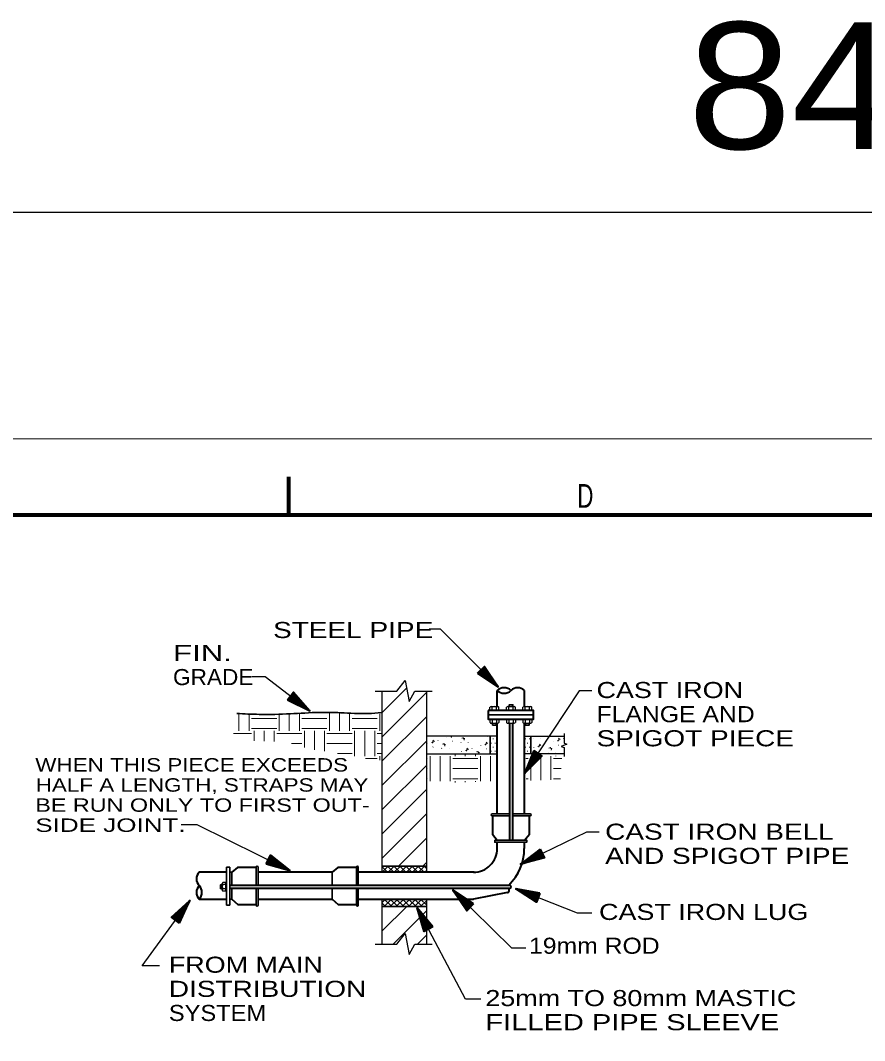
# Model space of a CAD drawing. Extents: x 55 to 190, y 198 to 264.
# Drawn here: x 89.01 to 102.33, y 248.35 to 264.46 of the extents above; entities that cross this region are included whole.
import ezdxf
from ezdxf.enums import TextEntityAlignment as Align

# ---------------------------------------------------------------- set-up
doc = ezdxf.new("R2010")
doc.units = 0
doc.header["$LTSCALE"] = 0.1
for name, color, linetype, lineweight in [('1', 7, 'Continuous', 25), ('2', 7, 'Continuous', 40), ('3', 7, 'Continuous', 25)]:
    doc.layers.add(name, color=color, linetype=linetype, lineweight=lineweight)

msp = doc.modelspace()

# ---------------------------------------------------------------- linework, layer by layer
at = {"layer": '1', "lineweight": 80}
msp.add_line((93.2427, 257.2525), (93.2427, 256.6525), dxfattribs=at)
at = {"layer": '1', "lineweight": 13}
msp.add_lwpolyline([(62.4915, 257.8525), (146.5927, 257.8525), (146.5927, 198.4512), (62.4915, 198.4512)], close=True, dxfattribs=at)
at = {"layer": '1', "lineweight": 80}
msp.add_lwpolyline([(65.1915, 256.6525), (145.3927, 256.6525), (145.3927, 199.6512), (65.1915, 199.6512)], close=True, dxfattribs=at)
at = {"layer": '2'}
for p, q in [((96.2788, 254.2066), (96.5497, 253.9364)), ((96.5497, 253.9364), (96.2925, 254.22)), ((96.5497, 253.9364), (96.319, 254.2465)), ((96.5497, 253.9364), (96.2391, 254.1666)), ((96.5497, 253.9364), (96.2539, 254.1822)), ((96.5497, 253.9364), (96.2663, 254.1939)), ((93.5769, 253.5602), (93.239, 253.748)), ((93.5769, 253.5602), (93.2514, 253.7652)), ((93.5769, 253.5602), (93.2623, 253.7785)), ((93.2729, 253.7928), (93.5769, 253.5602)), ((93.5769, 253.5602), (93.2848, 253.8078)), ((93.5769, 253.5602), (93.3075, 253.8375)), ((96.5354, 253.6266), (96.5354, 253.8803)), ((96.9622, 253.8803), (96.9622, 253.6266)), ((96.5354, 251.9311), (96.5354, 253.3652)), ((96.7302, 253.3636), (96.7302, 251.5184)), ((96.7802, 251.5184), (96.7802, 253.3636)), ((96.9622, 253.3636), (96.9622, 251.9311)), ((96.9638, 252.5691), (97.1278, 252.9191)), ((96.9638, 252.5691), (97.1461, 252.9077)), ((96.9638, 252.5691), (97.1599, 252.8979)), ((97.1749, 252.8881), (96.9638, 252.5691)), ((96.9638, 252.5691), (97.1908, 252.8773)), ((96.9638, 252.5691), (97.2218, 252.8566)), ((96.5354, 251.385), (96.5354, 251.4845)), ((96.9622, 251.4845), (96.9622, 251.385)), ((96.9011, 251.139), (97.221, 251.3562)), ((96.9011, 251.139), (97.2308, 251.3372)), ((96.9011, 251.139), (97.2376, 251.3215)), ((97.2456, 251.3057), (96.9011, 251.139)), ((93.2631, 251.0387), (92.8953, 251.1578)), ((93.2631, 251.0387), (92.9043, 251.1771)), ((93.2631, 251.0387), (92.9122, 251.1922)), ((92.9199, 251.2083), (93.2631, 251.0387)), ((93.2631, 251.0387), (92.9286, 251.2252)), ((93.2631, 251.0387), (92.9453, 251.2586)), ((96.9011, 251.139), (97.2538, 251.2882)), ((96.9011, 251.139), (97.2699, 251.2546)), ((92.2645, 251.0109), (91.8319, 251.0109)), ((93.9309, 251.0109), (92.7606, 251.0109)), ((96.17, 251.0109), (94.3439, 251.0109)), ((92.3124, 250.8085), (96.7257, 250.8085)), ((96.7257, 250.7553), (92.3151, 250.7553)), ((96.1076, 250.4569), (95.8348, 250.7252)), ((95.8348, 250.7252), (96.1322, 250.4815)), ((95.8348, 250.7252), (96.0677, 250.4167)), ((95.8348, 250.7252), (96.0938, 250.4434)), ((95.8348, 250.7252), (96.12, 250.4696)), ((95.8348, 250.7252), (96.147, 250.4971)), ((96.6955, 250.6879), (96.1613, 250.5839)), ((97.1815, 250.6096), (96.8257, 250.7503)), ((96.8257, 250.7503), (97.1945, 250.6418)), ((96.8257, 250.7503), (97.1604, 250.5572)), ((96.8257, 250.7503), (97.1741, 250.5918)), ((96.8257, 250.7503), (97.1879, 250.6262)), ((96.8257, 250.7503), (97.2019, 250.6619)), ((91.6827, 250.5619), (91.4118, 250.2865)), ((91.6827, 250.5619), (91.4417, 250.2643)), ((91.457, 250.2529), (91.6827, 250.5619)), ((91.6827, 250.5619), (91.4716, 250.2426)), ((91.6827, 250.5619), (91.4851, 250.232)), ((91.6827, 250.5619), (91.5028, 250.2198)), ((91.8319, 250.5839), (92.2645, 250.5839)), ((92.7612, 250.5839), (93.9309, 250.5839)), ((94.3439, 250.5839), (96.1613, 250.5839)), ((95.4499, 250.1113), (95.2702, 250.4492)), ((95.2702, 250.4492), (95.4808, 250.1275)), ((95.2702, 250.4492), (95.3998, 250.0852)), ((95.2702, 250.4492), (95.4329, 250.1026)), ((95.2702, 250.4492), (95.4657, 250.1201)), ((95.2702, 250.4492), (95.4996, 250.1381))]:
    msp.add_line(p, q, dxfattribs=at)
at = {"layer": '2', "lineweight": 13}
for p, q in [((94.7209, 253.5332), (95.1054, 253.9176)), ((94.7212, 253.1501), (95.4178, 253.847)), ((92.4593, 253.2414), (92.4593, 253.4988)), ((92.618, 253.2414), (92.618, 253.4988)), ((92.6577, 253.4398), (93.0546, 253.4398)), ((93.0943, 253.2414), (93.0943, 253.4946)), ((93.253, 253.2414), (93.253, 253.5028)), ((93.4118, 253.2414), (93.4118, 253.5107)), ((93.4515, 253.4398), (93.8483, 253.4398)), ((93.888, 253.2414), (93.888, 253.5184)), ((94.0468, 253.2414), (94.0468, 253.5189)), ((94.2055, 253.2414), (94.2055, 253.5216)), ((94.2452, 253.4398), (94.6421, 253.4398)), ((94.6818, 253.2414), (94.6818, 253.512)), ((94.7212, 252.767), (95.4178, 253.4639)), ((92.6577, 253.2811), (93.0546, 253.2811)), ((92.6974, 253.0858), (92.6974, 253.2414)), ((92.8561, 253.081), (92.8561, 253.2414)), ((93.0149, 253.076), (93.0149, 253.2414)), ((93.4515, 253.2811), (93.8483, 253.2811)), ((93.4911, 252.9805), (93.4911, 253.2414)), ((93.6499, 252.9432), (93.6499, 253.2414)), ((93.8086, 252.9215), (93.8086, 253.2414)), ((94.2452, 253.2811), (94.6421, 253.2811)), ((94.2849, 252.8445), (94.2849, 253.2414)), ((94.4436, 252.8445), (94.4436, 253.2414)), ((94.6024, 252.8445), (94.6024, 253.2414)), ((92.3712, 253.2017), (92.6577, 253.2017)), ((93.0546, 253.2017), (93.4515, 253.2017)), ((93.8483, 253.2017), (94.2452, 253.2017)), ((94.6421, 253.2017), (94.7024, 253.2017)), ((94.7212, 252.3841), (95.4178, 253.0808)), ((95.5184, 253.0776), (95.5112, 253.0469)), ((95.5432, 253.0736), (95.5202, 253.095)), ((95.5983, 253.0879), (95.6015, 253.0887)), ((95.7377, 253.1302), (95.7382, 253.1329)), ((95.8007, 253.1498), (95.8311, 253.1591)), ((95.82, 253.1601), (95.8152, 253.1395)), ((95.8271, 253.081), (95.8248, 253.0802)), ((96.0044, 253.1353), (95.974, 253.126)), ((95.9901, 253.1334), (96.0131, 253.112)), ((96.0118, 253.0943), (96.019, 253.1252)), ((96.2669, 253.1511), (96.265, 253.153)), ((96.3822, 253.1498), (96.3817, 253.1472)), ((96.4677, 253.1144), (96.4783, 253.1144)), ((96.5312, 253.1144), (96.5317, 253.1144)), ((96.976, 253.1144), (96.9863, 253.1144)), ((97.0392, 253.1144), (97.05, 253.1144)), ((97.1067, 253.1207), (97.1048, 253.1223)), ((97.1556, 253.1559), (97.1569, 253.1615)), ((97.2223, 253.1189), (97.2218, 253.1162)), ((97.4797, 253.0876), (97.5102, 253.0969)), ((97.5025, 253.1085), (97.4953, 253.0776)), ((97.5266, 253.1054), (97.5033, 253.1271)), ((97.5811, 253.1186), (97.584, 253.1194)), ((93.2885, 253.0429), (93.4515, 253.0429)), ((93.8483, 253.0429), (94.2452, 253.0429)), ((94.6421, 253.0429), (94.7024, 253.0429)), ((95.434, 253.0376), (95.4345, 253.04)), ((95.4972, 253.057), (95.5274, 253.0662)), ((95.5237, 252.9882), (95.521, 252.9874)), ((95.6594, 252.9651), (95.6575, 252.967)), ((95.7007, 253.0424), (95.6702, 253.0331)), ((95.6864, 253.0405), (95.7094, 253.0189)), ((95.7081, 253.0014), (95.7152, 253.0323)), ((95.7748, 252.9643), (95.7742, 252.9617)), ((95.9631, 253.0583), (95.9613, 253.0601)), ((95.97, 252.9138), (95.9708, 252.9162)), ((96.033, 252.9329), (96.0634, 252.9424)), ((96.0547, 252.954), (96.0475, 252.9231)), ((96.0793, 252.9501), (96.056, 252.9715)), ((96.0785, 253.057), (96.078, 253.0546)), ((96.1341, 252.9638), (96.1372, 252.9649)), ((96.2367, 252.9186), (96.2063, 252.9093)), ((96.2222, 252.917), (96.2455, 252.8953)), ((96.274, 253.0064), (96.2746, 253.0091)), ((96.3367, 253.0257), (96.3669, 253.035)), ((96.3584, 253.0466), (96.3513, 253.0157)), ((96.383, 253.0429), (96.3598, 253.0646)), ((96.3632, 252.9572), (96.3605, 252.9564)), ((96.436, 253.0509), (96.4465, 253.0509)), ((96.436, 252.9239), (96.4465, 252.9239)), ((96.4677, 252.9874), (96.4783, 252.9874)), ((96.4995, 253.0509), (96.51, 253.0509)), ((96.4995, 252.9239), (96.51, 252.9239)), ((96.5312, 252.9874), (96.532, 252.9874)), ((96.976, 252.9874), (96.9863, 252.9874)), ((97.0075, 253.0509), (97.018, 253.0509)), ((97.0075, 252.9239), (97.018, 252.9239)), ((97.0392, 252.9874), (97.05, 252.9874)), ((97.1141, 252.9754), (97.1146, 252.9781)), ((97.1763, 252.9948), (97.2064, 253.004)), ((97.1985, 253.0157), (97.1913, 252.9847)), ((97.2228, 253.0122), (97.1995, 253.0339)), ((97.2027, 252.9262), (97.2001, 252.9255)), ((97.2773, 253.0257), (97.2805, 253.0265)), ((97.3797, 252.9802), (97.3493, 252.971)), ((97.3657, 252.9794), (97.389, 252.9577)), ((97.3882, 252.9395), (97.3953, 252.9702)), ((97.4178, 253.0683), (97.4183, 253.0707)), ((97.5062, 253.0189), (97.5038, 253.0181)), ((94.0124, 252.8842), (94.2452, 252.8842)), ((94.4558, 252.8048), (94.6421, 252.8048)), ((94.6421, 252.8842), (94.7024, 252.8842)), ((94.6818, 252.7797), (94.6818, 252.8445)), ((95.4337, 252.8048), (95.4358, 252.8048)), ((95.4755, 252.4476), (95.4755, 252.8445)), ((95.6343, 252.4476), (95.6343, 252.8445)), ((95.793, 252.4476), (95.793, 252.8445)), ((95.8327, 252.8048), (96.2296, 252.8048)), ((95.8724, 252.8445), (95.8724, 252.8691)), ((96.0311, 252.8445), (96.0311, 252.8704)), ((96.1899, 252.8445), (96.1899, 252.8717)), ((96.2447, 252.8794), (96.2513, 252.9085)), ((96.2693, 252.4476), (96.2693, 252.8445)), ((96.428, 252.4476), (96.428, 252.8445)), ((96.9855, 252.8048), (97.0233, 252.8048)), ((97.063, 252.4579), (97.063, 252.8445)), ((97.2218, 252.4638), (97.2218, 252.8445)), ((97.339, 252.904), (97.3371, 252.9059)), ((97.3808, 252.4696), (97.3808, 252.8445)), ((97.4202, 252.8048), (97.5565, 252.8048)), ((97.4549, 252.9022), (97.4543, 252.8995)), ((97.4599, 252.8445), (97.4599, 252.8471)), ((94.7212, 252.001), (95.4178, 252.6976)), ((95.4337, 252.6461), (95.4358, 252.6461)), ((95.8327, 252.6461), (96.2296, 252.6461)), ((96.9895, 252.6461), (97.0233, 252.6461)), ((97.4202, 252.6461), (97.544, 252.6461)), ((95.4337, 252.4873), (95.4358, 252.4873)), ((95.8327, 252.4873), (96.2296, 252.4873)), ((95.8724, 252.4283), (95.8724, 252.4476)), ((96.0311, 252.4325), (96.0311, 252.4476)), ((96.1899, 252.4368), (96.1899, 252.4476)), ((96.9934, 252.4873), (97.0233, 252.4873)), ((97.4202, 252.4873), (97.5313, 252.4873)), ((94.7215, 251.6179), (95.4178, 252.3143)), ((94.7215, 251.2348), (95.4181, 251.9311)), ((94.9892, 251.1191), (95.4181, 251.548)), ((95.3649, 251.1117), (95.4181, 251.1649)), ((94.7209, 251.0136), (94.8143, 251.1067)), ((94.8053, 251.0109), (94.7212, 251.0948)), ((94.9011, 251.0109), (94.8051, 251.1067)), ((94.8141, 251.0109), (94.9101, 251.1067)), ((94.9969, 251.0109), (94.9008, 251.1067)), ((94.9098, 251.0109), (95.0059, 251.1067)), ((95.0927, 251.0109), (94.9969, 251.1067)), ((95.0059, 251.0109), (95.1017, 251.1067)), ((95.1884, 251.0109), (95.0927, 251.1067)), ((95.1017, 251.0109), (95.1974, 251.1067)), ((95.2842, 251.0109), (95.1884, 251.1067)), ((95.1974, 251.0109), (95.2932, 251.1067)), ((95.38, 251.0109), (95.2842, 251.1067)), ((95.2932, 251.0109), (95.389, 251.1067)), ((95.4178, 251.0686), (95.38, 251.1067)), ((95.389, 251.0109), (95.4178, 251.04)), ((94.7212, 250.5347), (94.7675, 250.581)), ((94.7741, 250.4672), (94.7212, 250.5201)), ((94.7495, 250.4672), (94.8633, 250.581)), ((94.8699, 250.4672), (94.7561, 250.581)), ((94.8453, 250.4672), (94.959, 250.581)), ((94.9657, 250.4672), (94.8519, 250.581)), ((94.9411, 250.4672), (95.0548, 250.581)), ((95.0614, 250.4672), (94.9477, 250.581)), ((95.0368, 250.4672), (95.1506, 250.581)), ((95.1572, 250.4672), (95.0435, 250.581)), ((95.1326, 250.4672), (95.2464, 250.581)), ((95.253, 250.4672), (95.1392, 250.581)), ((95.2284, 250.4672), (95.3422, 250.581)), ((95.3488, 250.4672), (95.235, 250.581)), ((95.3242, 250.4672), (95.4178, 250.5609)), ((95.4178, 250.4939), (95.3308, 250.581)), ((94.7212, 250.0849), (95.1056, 250.4696)), ((94.8945, 249.8751), (95.4181, 250.3987)), ((95.2771, 249.8745), (95.4178, 250.0153))]:
    msp.add_line(p, q, dxfattribs=at)
at = {"layer": '2', "lineweight": 25}
for p, q in [((94.7209, 251.0109), (94.7209, 253.8687)), ((95.4178, 253.8687), (95.4178, 251.0109)), ((96.4206, 253.5673), (96.4206, 253.6158)), ((96.4206, 253.5673), (96.5598, 253.5673)), ((96.4381, 253.6266), (96.5423, 253.6266)), ((96.4553, 253.5673), (96.4553, 253.6158)), ((96.5251, 253.5673), (96.5251, 253.6158)), ((96.5598, 253.5673), (96.5598, 253.6155)), ((96.6825, 253.5673), (96.6825, 253.6158)), ((96.6825, 253.5673), (96.8217, 253.5673)), ((96.7, 253.6266), (96.8043, 253.6266)), ((96.7172, 253.5673), (96.7172, 253.6158)), ((96.7871, 253.5673), (96.7871, 253.6158)), ((96.8217, 253.5673), (96.8217, 253.6155)), ((96.9413, 253.5673), (96.9413, 253.6158)), ((96.9413, 253.5673), (97.0805, 253.5673)), ((96.9588, 253.6266), (97.063, 253.6266)), ((96.976, 253.5673), (96.976, 253.6158)), ((97.0458, 253.5673), (97.0458, 253.6158)), ((97.0805, 253.5673), (97.0805, 253.6155)), ((96.4206, 253.4229), (96.5598, 253.4229)), ((96.4206, 253.4229), (96.4206, 253.3745)), ((96.4553, 253.4229), (96.4553, 253.3745)), ((96.5251, 253.4229), (96.5251, 253.3745)), ((96.5598, 253.4229), (96.5598, 253.3747)), ((96.6825, 253.4229), (96.8217, 253.4229)), ((96.6825, 253.4229), (96.6825, 253.3745)), ((96.7172, 253.4229), (96.7172, 253.3745)), ((96.7871, 253.4229), (96.7871, 253.3745)), ((96.8217, 253.4229), (96.8217, 253.3747)), ((96.9413, 253.4229), (97.0805, 253.4229)), ((96.9413, 253.4229), (96.9413, 253.3745)), ((96.976, 253.4229), (96.976, 253.3745)), ((97.0458, 253.4229), (97.0458, 253.3745)), ((97.0805, 253.4229), (97.0805, 253.3747)), ((96.4381, 253.3636), (96.5423, 253.3636)), ((96.7, 253.3636), (96.8043, 253.3636)), ((96.9588, 253.3636), (97.063, 253.3636)), ((96.5354, 253.1601), (95.4178, 253.1601)), ((96.9622, 253.1601), (97.5903, 253.1601)), ((95.4178, 252.8813), (96.5354, 252.8813)), ((97.5903, 252.8813), (96.9622, 252.8813)), ((92.1949, 250.7286), (92.1949, 250.8329)), ((92.2542, 250.8503), (92.2061, 250.8503)), ((92.2542, 250.7112), (92.2542, 250.8503)), ((92.2542, 250.8157), (92.2058, 250.8157)), ((92.2542, 250.7458), (92.2058, 250.7458)), ((92.2542, 250.7112), (92.2058, 250.7112)), ((94.7209, 249.8724), (94.7209, 250.581)), ((95.4178, 250.581), (95.4178, 249.8724))]:
    msp.add_line(p, q, dxfattribs=at)
at = {"layer": '2', "lineweight": 35}
for p, q in [((97.1072, 253.4951), (96.3949, 253.4951)), ((96.4227, 253.1593), (96.4227, 252.8815)), ((97.0667, 253.1601), (97.0667, 252.8815)), ((96.4558, 251.9311), (96.7302, 251.9311)), ((96.4558, 251.9013), (96.7302, 251.9013)), ((96.7802, 251.9311), (97.0551, 251.9311)), ((96.7802, 251.9013), (97.0551, 251.9013)), ((92.3468, 251.0109), (92.3127, 251.0109)), ((92.3468, 251.0109), (92.3468, 250.8083)), ((92.7297, 251.0906), (92.7297, 250.8064)), ((92.7596, 251.0906), (92.7596, 250.8064)), ((93.9301, 251.0109), (93.9301, 250.8083)), ((94.3129, 251.0906), (94.3129, 250.8085)), ((94.3428, 251.0906), (94.3428, 250.8085)), ((95.4178, 251.1067), (94.7215, 251.1067)), ((92.3468, 250.7553), (92.3468, 250.5823)), ((92.7297, 250.7575), (92.7297, 250.4913)), ((92.7596, 250.7575), (92.7596, 250.4913)), ((93.9301, 250.7553), (93.9301, 250.5823)), ((94.3129, 250.7553), (94.3129, 250.4913)), ((94.3428, 250.7553), (94.3428, 250.4913)), ((92.3468, 250.5836), (92.3127, 250.5836)), ((94.7215, 250.4672), (95.4178, 250.4672))]:
    msp.add_line(p, q, dxfattribs=at)
at = {"layer": '2', "lineweight": 25}
for points in [[(95.4583, 254.8521), (95.634, 254.8521), (96.5497, 253.9364)], [(92.6611, 254.0994), (92.8744, 254.0994), (93.5769, 253.5602)], [(94.6082, 253.8682), (94.9506, 253.8682), (95.0821, 254.0401), (95.1458, 253.7057), (95.235, 253.87), (95.5096, 253.87)], [(98.0301, 253.8737), (97.8292, 253.8737), (96.9638, 252.5691)], [(97.5911, 253.2033), (97.5911, 253.0493), (97.6343, 253.0347), (97.5459, 252.9937), (97.5932, 252.9815), (97.5932, 252.8379)], [(91.5446, 251.7663), (91.7954, 251.7663), (93.2631, 251.0387)], [(98.1428, 251.6409), (97.9422, 251.6409), (96.9011, 251.139)], [(96.9887, 249.8095), (96.763, 249.8095), (95.8348, 250.7252)], [(98.0301, 250.3614), (97.8041, 250.3614), (96.8257, 250.7503)], [(91.2059, 249.5335), (90.93, 249.5335), (91.6827, 250.5619)], [(96.2738, 249.0064), (96.0354, 249.0064), (95.2702, 250.4492)], [(94.6082, 249.8727), (94.9506, 249.8727), (95.0821, 250.0447), (95.1458, 249.7102), (95.235, 249.8745), (95.5096, 249.8745)]]:
    msp.add_lwpolyline(points, dxfattribs=at)
at = {"layer": '2'}
for points in [[(96.2253, 254.1529), (96.3338, 254.2611), (96.5497, 253.9364)], [(96.2253, 254.1529), (96.5497, 253.9364), (96.3058, 254.2336)], [(93.2271, 253.7324), (93.3205, 253.8539), (93.5769, 253.5602)], [(93.2271, 253.7324), (93.5769, 253.5602), (93.2961, 253.8229)], [(97.1117, 252.9299), (97.239, 252.845), (96.9638, 252.5691)], [(97.1117, 252.9299), (96.9638, 252.5691), (97.2067, 252.8672)], [(96.4616, 251.9013), (96.4616, 251.6097), (96.5354, 251.5184)], [(96.9627, 251.5184), (97.0458, 251.6107), (97.0458, 251.9013)], [(97.2125, 251.3737), (97.2787, 251.2358), (96.9011, 251.139)], [(97.2125, 251.3737), (96.9011, 251.139), (97.2622, 251.2713)], [(92.8866, 251.1403), (92.9548, 251.2774), (93.2631, 251.0387)], [(92.8866, 251.1403), (93.2631, 251.0387), (92.9368, 251.2424)], [(92.7297, 251.0847), (92.4381, 251.0847), (92.3468, 251.0109)], [(94.3129, 251.0847), (94.0214, 251.0847), (93.9301, 251.0109)], [(96.1605, 250.5109), (96.0528, 250.4021), (95.8348, 250.7252)], [(96.1605, 250.5109), (95.8348, 250.7252), (96.0809, 250.4296)], [(97.2093, 250.6799), (97.1524, 250.5379), (96.8257, 250.7503)], [(97.2093, 250.6799), (96.8257, 250.7503), (97.1675, 250.5741)], [(91.5184, 250.2082), (91.3951, 250.2989), (91.6827, 250.5619)], [(91.5184, 250.2082), (91.6827, 250.5619), (91.4263, 250.2754)], [(92.3468, 250.5836), (92.4392, 250.5005), (92.7297, 250.5005)], [(93.9301, 250.5836), (94.0224, 250.5005), (94.3129, 250.5005)], [(95.5168, 250.1471), (95.3813, 250.0756), (95.2702, 250.4492)], [(95.5168, 250.1471), (95.2702, 250.4492), (95.4162, 250.0936)]]:
    msp.add_lwpolyline(points, dxfattribs=at)
msp.add_lwpolyline([(96.3939, 253.5644), (96.3939, 253.4279), (97.1072, 253.4279), (97.1072, 253.5644)], close=True, dxfattribs=at)
at = {"layer": '2', "lineweight": 35}
for points in [[(96.781, 253.6269), (96.781, 253.656), (96.7236, 253.656), (96.7236, 253.6269)], [(96.519, 253.3633), (96.519, 253.3342), (96.4616, 253.3342), (96.4616, 253.3633)], [(97.0397, 253.3633), (97.0397, 253.3342), (96.9823, 253.3342), (96.9823, 253.3633)], [(92.1947, 250.8096), (92.1656, 250.8096), (92.1656, 250.7522), (92.1947, 250.7522)]]:
    msp.add_lwpolyline(points, dxfattribs=at)
for points in [[(96.4955, 251.5184), (96.4955, 251.4845), (97.0003, 251.4845), (97.0003, 251.5184)], [(92.2645, 251.0892), (92.2645, 250.491), (92.3124, 250.491), (92.3124, 251.0892)]]:
    msp.add_lwpolyline(points, close=True, dxfattribs=at)
at = {"layer": '2'}
for centre, radius, start, end in [((96.6427, 253.7694), 0.1543, 45.9775, 134.02119), ((96.8571, 253.7694), 0.1543, 45.97881, 134.0225), ((96.6427, 253.9913), 0.1543, 225.97881, 314.0225), ((96.1612, 251.385), 0.3742, 269.9847, 360), ((96.1612, 251.385), 0.8011, 313.97386, 0.00182), ((91.9429, 250.9056), 0.1543, 135.97881, 224.0225), ((91.9429, 250.6911), 0.1543, 135.9775, 224.02119), ((91.721, 250.6911), 0.1543, 315.97881, 44.0225), ((96.691, 250.7215), 0.0339, 277.69693, 91.68872), ((96.7257, 250.7819), 0.0266, 270, 90)]:
    msp.add_arc(centre, radius, start, end, dxfattribs=at)
at = {"layer": '2', "lineweight": 25}
for centre, radius, start, end in [((96.4379, 253.6069), 0.0195, 27.8877, 152.03419), ((96.4901, 253.5621), 0.0643, 57.00616, 122.94297), ((96.5423, 253.6068), 0.0195, 26.78269, 151.8391), ((96.6999, 253.6069), 0.0195, 27.8877, 152.03419), ((96.7521, 253.5621), 0.0643, 57.00616, 122.94297), ((96.8043, 253.6068), 0.0195, 26.78269, 151.8391), ((96.9586, 253.6069), 0.0195, 27.8877, 152.03419), ((97.0108, 253.5621), 0.0643, 57.00616, 122.94297), ((97.063, 253.6068), 0.0195, 26.78269, 151.8391), ((96.4379, 253.3833), 0.0195, 207.96581, 332.1123), ((96.4901, 253.4281), 0.0643, 237.05703, 302.99384), ((96.5423, 253.3834), 0.0195, 208.1609, 333.21731), ((96.6999, 253.3833), 0.0195, 207.96581, 332.1123), ((96.7521, 253.4281), 0.0643, 237.05703, 302.99384), ((96.8043, 253.3834), 0.0195, 208.1609, 333.21731), ((96.9586, 253.3833), 0.0195, 207.96581, 332.1123), ((97.0108, 253.4281), 0.0643, 237.05703, 302.99384), ((97.063, 253.3834), 0.0195, 208.1609, 333.21731), ((92.2148, 250.8329), 0.0195, 116.78269, 241.8391), ((92.2146, 250.7285), 0.0195, 117.8877, 242.03419), ((92.2595, 250.7807), 0.0643, 147.00616, 212.94297)]:
    msp.add_arc(centre, radius, start, end, dxfattribs=at)
at = {"layer": '2', "lineweight": 35}
for centre, start, end in [((96.4558, 251.9162), 90, 270), ((97.0551, 251.9162), 270, 90), ((92.7446, 251.0906), 0, 180), ((94.3279, 251.0906), 0, 180), ((92.7446, 250.4913), 180, 0), ((94.3279, 250.4913), 180, 0)]:
    msp.add_arc(centre, 0.0149, start, end, dxfattribs=at)
msp.add_spline([(94.7119, 253.5337), (94.4974, 253.5163), (94.0634, 253.5292), (93.7258, 253.5337), (93.2699, 253.5118), (92.7791, 253.503), (92.4241, 253.5163)], degree=3, dxfattribs=at)
at = {"layer": '3'}
msp.add_line((62.4915, 261.4312), (146.5927, 261.4312), dxfattribs=at)

# ---------------------------------------------------------------- texts
at = {"layer": '1', "width": 0.7}
msp.add_text('D', height=0.375, dxfattribs=at).set_placement((97.9255, 256.765), align=Align.CENTER)
at = {"layer": '2'}
for s, height, width, p in [('STEEL PIPE', 0.254, 1.3, (92.9977, 254.7079)), ('FIN. ', 0.254, 1.45, (91.4184, 254.3457)), ('GRADE', 0.254, 1.05, (91.4184, 253.9647)), ('CAST IRON', 0.254, 1.25, (98.102, 253.7605)), ('FLANGE AND', 0.254, 1.15, (98.102, 253.3795)), ('SPIGOT PIECE', 0.254, 1.3, (98.102, 252.9985)), ('WHEN THIS PIECE EXCEEDS', 0.2117, 1.25, (89.2451, 252.6)), ('HALF A LENGTH, STRAPS MAY', 0.2117, 1.25, (89.2514, 252.2825)), ('BE RUN ONLY TO FIRST OUT-', 0.2117, 1.3, (89.2451, 251.965)), ('SIDE JOINT.', 0.2117, 1.45, (89.2451, 251.6475)), ('CAST IRON BELL', 0.254, 1.3, (98.238, 251.5232)), ('AND SPIGOT PIPE', 0.254, 1.3, (98.238, 251.1422)), ('CAST IRON LUG', 0.254, 1.25, (98.1415, 250.2566)), ('19mm ROD', 0.254, 1.15, (97.0363, 249.7227)), ('FROM MAIN ', 0.254, 1.25, (91.3525, 249.4232)), ('DISTRIBUTION', 0.254, 1.3, (91.3525, 249.0422)), ('25mm TO 80mm MASTIC', 0.254, 1.25, (96.3471, 248.8961)), ('SYSTEM', 0.254, 1.1, (91.3525, 248.6611)), ('FILLED PIPE SLEEVE', 0.254, 1.35, (96.3471, 248.5151))]:
    msp.add_text(s, height=height, dxfattribs=dict(at, width=width)).set_placement(p)
at = {"layer": '3', "width": 1.1}
msp.add_text('841mm', height=2, dxfattribs=at).set_placement((99.5415, 262.4312))

doc.saveas('drawing.dxf')
